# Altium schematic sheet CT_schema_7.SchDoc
size 402 x 220 mm
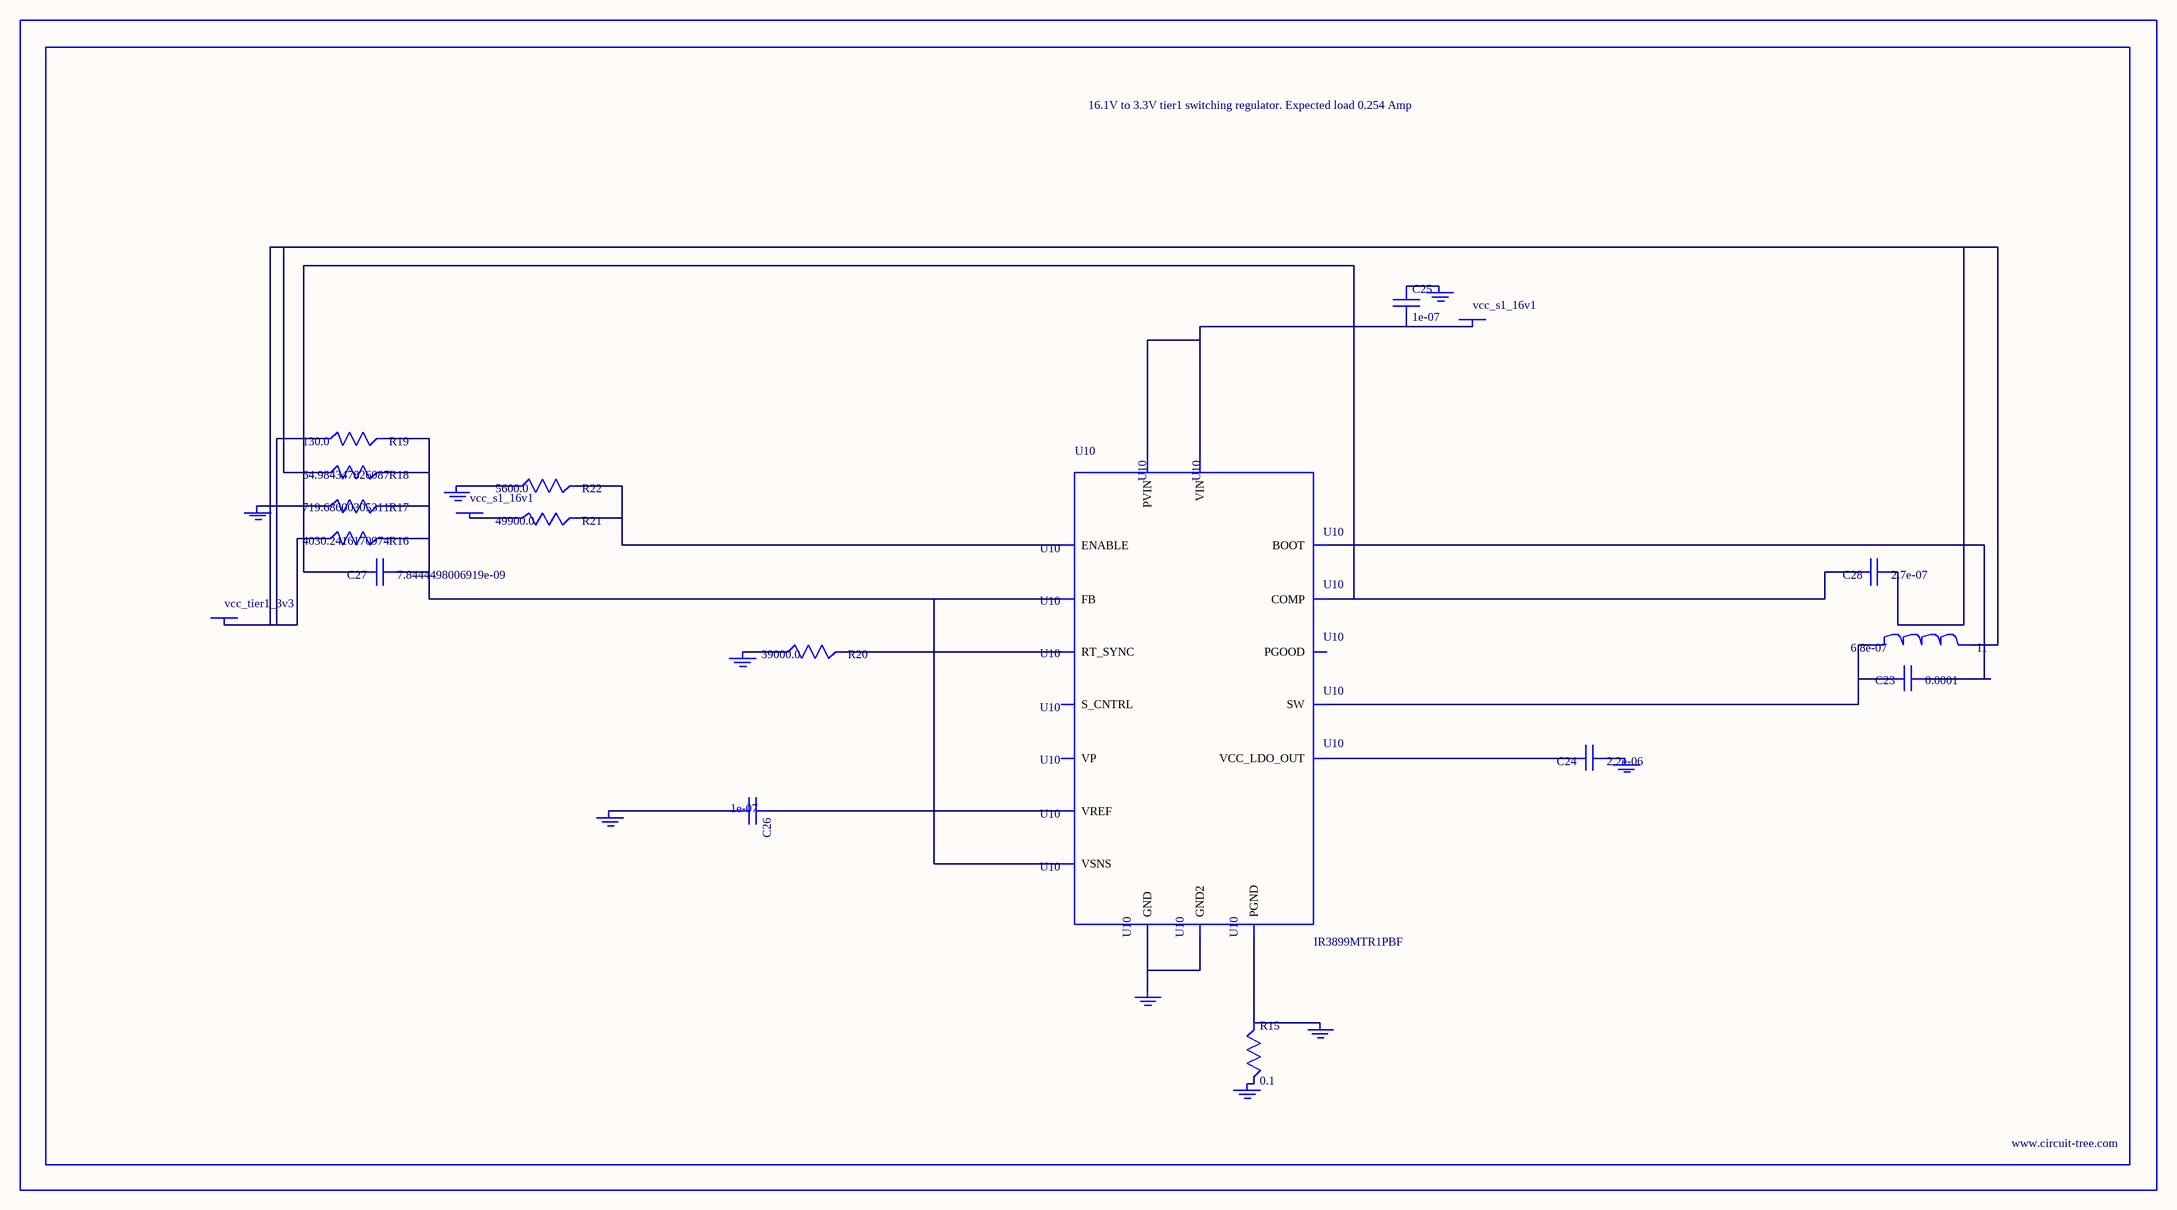
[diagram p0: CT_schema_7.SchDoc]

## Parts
BORDER6  (no value)
C23  0.0001  [C1210]
C24  2.2e-06  [C0603]
C25  1e-07  [C0402]
C26  1e-07  [C0402]
C27  7.8444498006919e-09  [R0603]
C28  2.7e-07  [C0603]
GND_INSTANCE_6_0  (no value)
GND_INSTANCE_6_1  (no value)
GND_INSTANCE_6_2  (no value)
GND_INSTANCE_6_3  (no value)
GND_INSTANCE_6_4  (no value)
GND_INSTANCE_6_5  (no value)
GND_INSTANCE_6_6  (no value)
GND_INSTANCE_6_7  (no value)
GND_INSTANCE_6_8  (no value)
I1  6.8e-07  [IND25X25CZ]
POWER_INSTANCE_6_0  vcc_s1_16v1
POWER_INSTANCE_6_1  vcc_s1_16v1
POWER_INSTANCE_6_2  vcc_tier1_3v3
R15  0.1  [R0603]
R16  4030.2416170974  [R0603]
R17  719.68600305311  [R0603]
R18  64.984347826087  [R0603]
R19  130.0  [R0603]
R20  39000.0  [R0603]
R21  49900.0  [R0603]
R22  5600.0  [R0603]
U10  IR3899MTR1PBF  [IR3899MTR1PBF]

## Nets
NetC23_1: C23.1 U10.14(BOOT)
NetC23_2: C23.2 I1.1 U10.12(SW)
NetC24_1: C24.1 GND_INSTANCE_6_4.0(GND)
NetC24_2: C24.2 U10.10(VCC_LDO_OUT)
NetC25_1: C25.1 GND_INSTANCE_6_3.0(GND)
NetC25_2: C25.2 POWER_INSTANCE_6_0.0(PWR) U10.9(VIN) U10.13(PVIN)
NetC26_1: C26.1 U10.2(VREF)
NetC26_2: C26.2 GND_INSTANCE_6_1.0(GND)
NetC27_1: C27.1 R16.2 R17.2 R18.2 R19.2 U10.1(FB) U10.8(VSNS)
NetC27_2: C27.2 C28.2 U10.3(COMP)
NetC28_1: C28.1 I1.2 POWER_INSTANCE_6_2.0(PWR) R16.1 R18.1 R19.1
NetGND_INSTANCE_6_0_0: GND_INSTANCE_6_0.0(GND) R17.1
NetGND_INSTANCE_6_2_0: GND_INSTANCE_6_2.0(GND) R20.1
NetGND_INSTANCE_6_5_0: GND_INSTANCE_6_5.0(GND) R15.2
NetGND_INSTANCE_6_6_0: GND_INSTANCE_6_6.0(GND) R15.1 U10.11(PGND)
NetGND_INSTANCE_6_7_0: GND_INSTANCE_6_7.0(GND) R22.1
NetGND_INSTANCE_6_8_0: GND_INSTANCE_6_8.0(GND) U10.4(GND) U10.17(GND2)
NetPOWER_INSTANCE_6_1_0: POWER_INSTANCE_6_1.0(PWR) R21.1
NetR20_2: R20.2 U10.5(RT_SYNC)
NetR21_2: R21.2 R22.2 U10.15(ENABLE)

Not connected (* = marked no-connect by the designer): U10 6(S_CNTRL) 7(PGOOD) 16(VP)

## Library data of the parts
BORDER6 = BORDER_PAGE6
C23 = GRM32ER61A107ME20L
C24 = C0603C225K8RACTU
C25 C26 = C0402C104K3RACTU
C27 = C27
C28 = C0603C274K3RAC
GND_INSTANCE_6_0-GND_INSTANCE_6_8 = GND
I1 = IHLP2525CZERR68M01
POWER_INSTANCE_6_0-POWER_INSTANCE_6_2 = PWR
R15 = ERJ-3RSFR10V
R16 = R16
R17 = R17
R18 = R18
R19 = RC0603JR-07130RL
R20 = RC0603JR-0739KL
R21 = RC0603FR-0749K9
R22 = RC0603JR-075K6L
